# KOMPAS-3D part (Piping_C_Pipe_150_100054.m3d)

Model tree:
1. Plane XY
2. Plane ZX
3. Plane ZY
4. X Axis
5. Y Axis
6. Z Axis
7. Origin
8. Path  (labels: Тройник Dy 150; Труба Dy 150; Отвод 90 Dy 150)
9. Plane of section
10. Section of pipe
11. Pipe
     Толщина стенки 1 = 1

Referenced files in C:\Program Files\ASCON\KOMPAS-3D V10\Libs\Piping\Models\Tanks\: Tanks.a3d
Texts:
  Pipe Dn 150
  Steel ASTM A295
  Three Point Plane
  Plane at Angle
  Line and Point Plane
  Axis through Two Vertices
  Axis of Feature
  Axis of Conical Surface
  Axis through Edge
  Приклеить элемент выдавливания
  Приклеить элемент вращения
  Приклеить кинематический элемент
  Приклеить элемент по сечениям
  Trim by Surface
  Trim by Sketch
  Feature with No History
  Intersection Axis of Two Planes
  Two Line Plane
  Line and Face Plane
  Bend by line
  Hole in sheet body
  Cut in sheet body
  Point in CM
  Linear Dimension from Line to Point
  Surface Finish Symbol
  Geometric Tolerance Symbol
  Текст на чертеже
  Линия-выноска #1
  Линия-выноска #2
  Линия-выноска #3
  Отклонения формы и база
  Марка координационной оси
  Марка/позиционное обозначение с линией-выноской
  Марка/позиционное обозначение на линии
  Марка/позиционное обозначение без линии-выноски
  Тройник Dy 150
  Труба Dy 150
  Отвод 90 Dy 150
